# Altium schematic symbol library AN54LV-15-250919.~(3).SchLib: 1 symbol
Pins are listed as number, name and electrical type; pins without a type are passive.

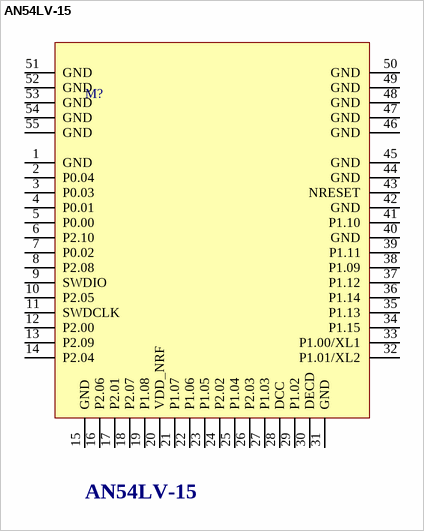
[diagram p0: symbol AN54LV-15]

## AN54LV-15
designator M?
footprint PCB_MDBT42Q_32_10X16
footprint AN54LV-15
pins: 1 GND, 2 P0.04, 3 P0.03, 4 P0.01  , 5 P0.00, 6 P2.10, 7 P0.02, 8 P2.08, 9 SWDIO, 10 P2.05, 11 SWDCLK, 12 P2.00, 13 P2.09, 14 P2.04, 15 GND, 16 P2.06, 17 P2.01, 18 P2.07, 19 P1.08, 20 VDD_NRF, 21 P1.07, 22 P1.06, 23 P1.05, 24 P2.02, 25 P1.04, 26 P2.03, 27 P1.03, 28 DCC, 29 P1.02, 30 DECD, 31 GND, 32 P1.01/XL2, 33 P1.00/XL1, 34 P1.15, 35 P1.13, 36 P1.14, 37 P1.12, 38 P1.09, 39 P1.11, 40 GND, 41 P1.10, 42 GND, 43 NRESET, 44 GND, 45 GND, 46 GND, 47 GND, 48 GND, 49 GND, 50 GND, 51 GND, 52 GND, 53 GND, 54 GND, 55 GND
